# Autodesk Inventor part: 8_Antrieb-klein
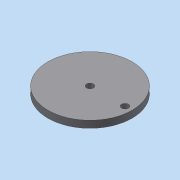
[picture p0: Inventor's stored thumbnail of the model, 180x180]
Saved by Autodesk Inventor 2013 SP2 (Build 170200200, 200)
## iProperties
Created: 2014-01
Part Number: 8_Antrieb-klein
Material: Allgemein
Document SubType Name: Modeling
Designer: J. Palme
Density: 1 g/cm^3
Author: J. Palme
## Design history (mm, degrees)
sketch "Skizze1"
  geometry: C1 r 0.5 at (0, 0); C2 r 0.5 at (5, 0); C3 r 6 at (0, 0); 1 further point
  constraints: 3 centre point, 2 coincident, 1 equal radius, 1 horizontal alignment
  dimensions: "d0" = 5 distance of C2.centre C1.centre; "d4" = 1 diameter of C1; "d5" = 12 diameter of C3
extrude "Extrusion1" new body sketch "Skizze1" distance "d2" = 1; taper "d3" = 0 deg
node "Volumenkörper1"
